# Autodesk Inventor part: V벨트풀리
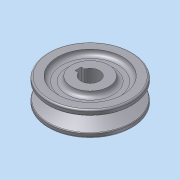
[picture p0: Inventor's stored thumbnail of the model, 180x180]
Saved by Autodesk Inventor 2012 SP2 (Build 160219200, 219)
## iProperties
Created: 2015-03
Part Number: V벨트풀리
Material: 강
Document SubType Name: Modeling
Designer: KYOUNG IL JANG
Density: 1 g/cm^3
CustomPartVersion: 1
Author: KYOUNG IL JANG
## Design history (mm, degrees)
sketch "주 스케치"
  geometry: L1 (0, 16)-(27, 16); L2 (27, 16)-(27, 12.861); L3 (27, 12.861)-(16, 9.498); L4 (16, 9.498)-(16, 6.502); L5 (16, 6.502)-(27, 3.139); L6 (27, 3.139)-(27, 0); L7 (27, 0)-(0, 0); L8 (25, 12.25)-(25, 3.75); L9 (16, 8)-(25, 8); L10 (27, 12.861)-(27, 3.139); L11 (0, -3)-(0, 18) reference; L12 (0, 0)-(0, 16)
  constraints: 22 end point, 5 perpendicular, 2 collinear, 2 midpoint, 2 point on line, 1 parallel
  dimensions: "d0" = 8.5 distance of L8.start L8.end (= da_Bw); "d1" = 34 deg angle of L3 L5 (= da_Alfa); "d2" = 2 distance between parallel lines of L2 L8 (= da_c); "d6" = 16 distance between parallel lines of L7 L1 (computed from d5, da_ng, da_Sg); "d21" = 50 diameter of L8 L11 (= da_Dw); "d25" = 11 distance between parallel lines of L4 L10 (= da_Hd); "d27" = 8 distance between parallel lines of L7 L9 (= da_Se)
node "벨트 평면"
revolve "본체" stored, may be unused: angle "d7" = 90 deg
revolve "그루브" stored, may be unused: angle "d15" = 90 deg
feature "허브 키홈"
fillet "모깎기3" dims "d28" = 0.5, "d29" = 1, "d30" = 1
sketch "스케치2"
  geometry: C1 r 12 at (0, 0); C2 r 21 at (0, 0); 1 further point
  constraints: 2 centre point, 2 coincident
  dimensions: "d31" = 24 diameter of C1; "d32" = 42 diameter of C2
extrude "돌출1" cut sketch "스케치2" distance "d33" = 3; taper "d34" = 0 deg
fillet "모깎기4" dims "d35" = 3
node "작업 평면2"
body "Solid1"
pattern_linear "그루브 패턴" dims "d18" = 12 (= da_Sg)
mirror "대칭1"
other parameters: "d5" = 8 (= da_Se), "da_Bw" = 8.5 [user parameter; used in 1 equation term], "da_Alfa" = 34 deg [user parameter; used in 1 equation term], "da_c" = 2 [user parameter; used in 1 equation term], "da_Dw" = 50 [user parameter; used in 1 equation term], "da_Hd" = 11 [user parameter; used in 1 equation term], "da_Se" = 8 [user parameter; used in 2 equation terms], "da_Sg" = 12 [user parameter; used in 2 equation terms], "da_r1" = 0 [user parameter], "da_r2" = 0 [user parameter], "d24" = 0, "d26" = 0
